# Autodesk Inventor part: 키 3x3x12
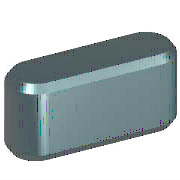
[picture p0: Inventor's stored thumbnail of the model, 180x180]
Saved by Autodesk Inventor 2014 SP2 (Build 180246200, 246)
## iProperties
Created: 2012-02
Part Number: 키 3x3x12
Material: 강철, 연강
Description: 키 및 해당 키홈
Document SubType Name: Modeling
Standard: KS B 1311
Designer: mduedu
Standards Organization: KS
Language: ko-KR
Size Designation: 3 x 3 x 12
Categories: <MemberInstance><Categories><Category DisplayName="샤프트 부품" InternalName="7f7aeb1f-a693-4053-b835-cee3144e0d98" Mnemonic="SHFT"><Category DisplayName="키" Interna
Density: 1 g/cm^3
Appearance: 노란색
IsCustomPart: 1
Author: mduedu
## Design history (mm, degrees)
workplane "Work Plane1"
workplane "Work Plane2"
sketch "스케치1"
  geometry: L1 (1.5, 1.5)-(10.5, 1.5); L2 (10.5, -1.5)-(1.5, -1.5); L3 (0, 9.4)-(0, -7.4) reference; L4 (-5, 0)-(30, 0) reference; L5 (12, 0)-(12, 7); A1 r 1.5 centre (1.5, 0) between (1.5, 1.5) and (1.5, -1.5); A2 r 1.5 centre (10.5, 0) between (10.5, -1.5) and (10.5, 1.5)
  constraints: 6 end point, 5 point on circle, 4 tangent, 3 point on line, 2 centre point, 1 horizontal, 1 parallel, 1 perpendicular
  dimensions: "d0" = 1.5 radius of A1 (= 0.5 x PB); "d13" = 1.5 radius of A2 (= 0.5 x PB); "d14" = 12 distance between parallel lines of L5 L3 (= NLG)
extrude "본체1" new body sketch "스케치1" taper "d3" = 0 deg; stored distance "d4" = 10
workplane "Work Plane3"
body "Solid1"
chamfer "모따기1" distance "d8" = 0.25 (= PHH); stored, may be unused: second distance "d9" = 0.25 (= PHH), angle "d15" = 45 deg
other parameters: "d1" = -1.8 (= -PNT), "d2" = 1.2 (= PH - PNT), "NLG" = 12 [user parameter; used in 3 equation terms], "PB" = 3 [user parameter; used in 2 equation terms], "PNT" = 1.8 [user parameter; used in 2 equation terms], "PH" = 3 [user parameter; used in 1 equation term], "PHH" = 0.25 [user parameter; used in 2 equation terms], "d10" = 0, "d16" = 0, "d17" = 0, "d18" = 0, "WDMIN" = 8 [user parameter], "PLB2" = 12 (= NLG) [user parameter], "PLB1" = 12 (= NLG) [user parameter], "RR" = 0.08 [user parameter], "PUEB" = 1.4 [user parameter]
